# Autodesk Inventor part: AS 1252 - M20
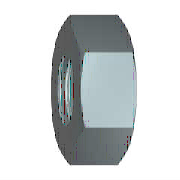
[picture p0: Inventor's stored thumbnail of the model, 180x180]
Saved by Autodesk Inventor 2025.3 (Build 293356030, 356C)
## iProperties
IsCustomPart: 0
Created: 2024-01
Part Number: AS 1252 - M20
Material: Acero, suave
Description: Pernos de acero Perno hex
Document SubType Name: Modeling
Standard: AS 1252
Designer: User
Standards Organization: AS
Language: es-ES
Size Designation: M20
Categories: <MemberInstance><Categories><Category DisplayName="Fijaciones" InternalName="e4da775c-781d-43d5-af7c-5136215cf5a6" Mnemonic="FSTN"><Category DisplayName="Tuerca
Density: 7.85 g/cm^3
Appearance: Semipulido
Author: User
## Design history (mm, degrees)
body "Solid1"
workaxis "Work Axis1"
workplane "Work Plane1"
sketch "Boceto1"
  geometry: L1 (-18.475, 0)-(-9.238, 16); L2 (-9.238, 16)-(9.238, 16); L3 (9.238, 16)-(18.475, 0); L4 (18.475, 0)-(9.238, -16); L5 (9.238, -16)-(-9.238, -16); L6 (-9.238, -16)-(-18.475, 0); 2 further points
  constraints: 12 end point, 1 coincident, 1 horizontal, 11 other
  dimensions: "d0" = 36.95042 distance of L3.end L1.start (= 1.1547 x SW)
extrude "Cuerpo" new body sketch "Boceto1" distance "d1" = 21.3 (= KOH); taper "d2" = 0 deg
revolve "Chaflán1" stored, may be unused: angle "d7" = 90 deg
sketch "Boceto3"
  geometry: A1 r 16 centre (0, 0) between (-8, -13.856) and (8, -13.856) reference; 1 further point
  constraints: 1 coincident
hole "Rosca" sketch "Boceto3" diameter "d25" = 17.294; stored, may be unused: countersink angle "d29" = 82 deg, drill point angle "d31" = 118 deg; dims "d26" = 6, "d27" = 4, "d28" = 2, "d30" = 8
chamfer "Chaflán2" distance "d8" = 1.35316 (= -0.5 x GD1 + 0.5 x NND); stored, may be unused: angle "d9" = 30 deg, second distance "d40" = 1.35316 (= -0.5 x GD1 + 0.5 x NND)
chamfer "Chaflán3" distance "d10" = 1.35316 (= -0.5 x GD1 + 0.5 x NND); stored, may be unused: angle "d11" = 30 deg, second distance "d41" = 1.35316 (= -0.5 x GD1 + 0.5 x NND)
sketch "Boceto2"
  geometry: L1 (0, 9.238)-(0, 18.475) reference; L2 (0, 18.475)-(21.3, 18.475) reference; L3 (21.3, 9.238)-(21.3, 18.475) reference; L4 (-4.26, 0)-(25.56, 0) reference; L5 (1.429, 18.475)-(0, 16); L6 (19.871, 18.475)-(21.3, 16)
  constraints: 4 end point, 4 point on line
  dimensions: "d3" = 30 deg angle of L1 L5 (= ANG1); "d4" = 30 deg angle of L3 L6 (= ANG2); "d5" = 32 diameter of L5.end L4 (= SW0); "d6" = 32 diameter of L6.end L4 (= SW01)
other parameters: "ANG1" = 30 deg [user parameter; used in 1 equation term], "ANG2" = 30 deg [user parameter; used in 1 equation term], "KOH" = 21.3 [user parameter; used in 1 equation term], "SW" = 32 [user parameter; used in 4 equation terms], "SW0" = 32 (= SW) [user parameter; used in 1 equation term], "SW01" = 32 (= SW) [user parameter; used in 1 equation term], "GD1" = 17.29367 (computed from THREADDIA, PTC, TOA) [user parameter; used in 4 equation terms], "d13" = 0, "d14" = 0, "d39" = 0, "d42" = 0, "GUL" = 1.35317 (= 0.541266 x PTC) [user parameter], "TPU" = 4 (computed from PTC) [user parameter], "WFT" = 0.8 [user parameter], "TOA" = 30 deg [user parameter; used in 1 equation term], "PTC" = 2.5 [user parameter; used in 4 equation terms], "E0" = 36.96 (= 1.155 x SW) [user parameter], "GAL" = 1.35317 (= 0.541266 x PTC) [user parameter]
